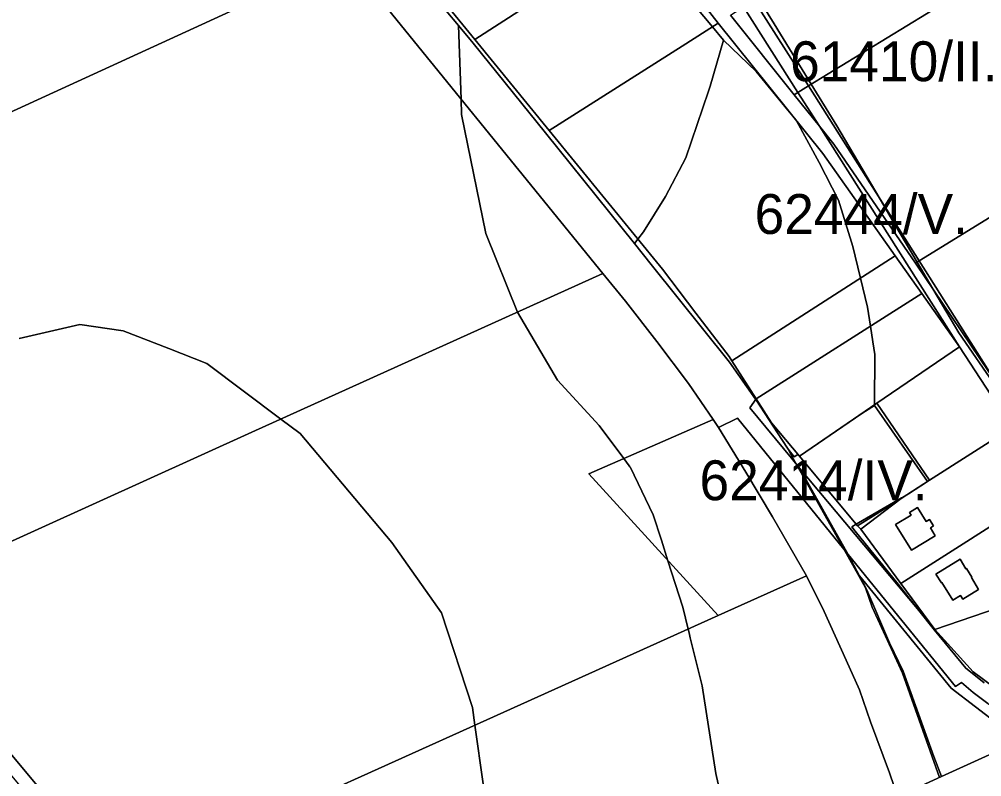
# Model space of a CAD drawing. Extents: x -522079 to -518792, y -1142400 to -1139961.
# Drawn here: x -520985.3 to -520623.1, y -1140806 to -1140520.9 of the extents above; entities that cross this region are included whole.
import ezdxf

# ---------------------------------------------------------------- set-up
doc = ezdxf.new("R2010")
doc.units = 0
for name, color, linetype in [('Hranice parcel', 7, 'Continuous'), ('Parcelní čísla', 7, 'Continuous'), ('Poz předměty', 7, 'Continuous'), ('Značky bodu BP', 7, 'Continuous'), ('Značky kultur', 7, 'Continuous')]:
    doc.layers.add(name, color=color, linetype=linetype)

msp = doc.modelspace()

# ---------------------------------------------------------------- linework, layer by layer
at = {"layer": 'Hranice parcel'}
for points in [[(-520837.71, -1140499.35), (-520813.81, -1140528.62), (-520785.9, -1140562.81), (-520743.28, -1140615.01), (-520730.64, -1140631.58), (-520718.15, -1140647.9), (-520717.09, -1140649.55), (-520707.94, -1140663.79), (-520710.41, -1140667.24), (-520694.71, -1140686.16), (-520691.52, -1140689.98), (-520673.31, -1140722.41), (-520715.02, -1140671.04), (-520722.11, -1140674.56), (-520724.12, -1140671.61), (-520733.42, -1140657.97), (-520745.42, -1140642.26), (-520757.18, -1140627.06), (-520765.71, -1140616.57), (-520862.22, -1140497.87)], [(-520620.79, -1140778.52), (-520626.26, -1140774.29), (-520630.76, -1140770.61), (-520632.98, -1140772.07), (-520673.31, -1140722.41), (-520691.52, -1140689.98), (-520667.53, -1140718.71), (-520640.71, -1140750.61), (-520626.37, -1140766.52), (-520614.11, -1140775.58)], [(-520987.34, -1140960.66), (-520896.33, -1140923.45), (-520882.47, -1140917.37), (-520708.35, -1140837.86), (-520654.73, -1140813.47), (-520638.22, -1140805.93), (-520618.93, -1140797.21)]]:
    msp.add_lwpolyline(points, dxfattribs=at)
for points in [[(-520708.82, -1140513.67), (-520688.32, -1140546.05), (-520692.27, -1140548.47), (-520712.75, -1140516.21)], [(-520688.32, -1140546.05), (-520646.64, -1140611.87), (-520648.02, -1140612.72), (-520678.73, -1140568), (-520684.19, -1140561.2), (-520692.27, -1140548.47)], [(-520581.36, -1140753.24), (-520579.16, -1140744.51), (-520580.56, -1140740.45), (-520583.71, -1140731.03), (-520599.29, -1140698.77), (-520608.35, -1140679.79), (-520611.7, -1140674.57), (-520631.48, -1140644.23), (-520684.19, -1140561.2), (-520678.73, -1140568), (-520648.02, -1140612.72), (-520617.05, -1140658.61), (-520605.12, -1140676.44), (-520598.21, -1140690.89), (-520586.97, -1140713.22), (-520580.64, -1140725.97), (-520577.29, -1140732.42), (-520576.44, -1140734.91), (-520575.25, -1140739.5), (-520574.04, -1140754.01), (-520579.46, -1140756.88), (-520580.35, -1140753)], [(-520646.64, -1140611.87), (-520617.05, -1140658.61), (-520648.02, -1140612.72)], [(-520691.52, -1140689.98), (-520694.71, -1140686.16), (-520710.41, -1140667.24), (-520707.94, -1140663.79), (-520702.26, -1140672.84), (-520691.74, -1140685.4), (-520669.79, -1140711.59), (-520668.57, -1140712.91), (-520653.49, -1140733.31), (-520640.71, -1140750.61), (-520667.53, -1140718.71)], [(-520691.74, -1140685.4), (-520662.52, -1140665.44), (-520642.72, -1140694.43), (-520653.44, -1140701.29), (-520669.79, -1140711.59)], [(-520657.77, -1140804.5), (-520664.94, -1140785.33), (-520669.15, -1140773.31), (-520674.16, -1140762.17), (-520682.43, -1140743.84), (-520689.02, -1140730.38), (-520701.8, -1140708.2), (-520711.88, -1140691.39), (-520722.11, -1140674.56), (-520715.02, -1140671.04), (-520673.31, -1140722.41), (-520669.12, -1140730.36), (-520666.3, -1140735.71), (-520657.82, -1140755.57), (-520652.69, -1140766.32), (-520641.11, -1140798.37), (-520638.22, -1140805.93), (-520654.73, -1140813.47), (-520656.02, -1140809.72)], [(-520655.5, -1140711.11), (-520649.68, -1140707.57), (-520650.3, -1140706.56), (-520647.28, -1140704.72), (-520644.04, -1140709.99), (-520642.78, -1140709.18), (-520641.28, -1140711.57), (-520642.42, -1140712.34), (-520640.64, -1140715.35), (-520649.51, -1140720.81)], [(-520594.41, -1140790.88), (-520595.39, -1140795.43), (-520616.33, -1140786.69), (-520634.59, -1140772.65), (-520669.12, -1140730.36), (-520673.31, -1140722.41), (-520632.98, -1140772.07), (-520630.76, -1140770.61), (-520626.26, -1140774.29), (-520620.79, -1140778.52), (-520609.47, -1140785.27), (-520604.74, -1140787.54), (-520595.11, -1140790.67)], [(-520624.28, -1140735.5), (-520630.26, -1140739.15), (-520631.05, -1140737.86), (-520633.92, -1140739.62), (-520638.05, -1140732.94), (-520638.3, -1140733.1), (-520640.31, -1140729.84), (-520631.24, -1140724.18), (-520629.04, -1140727.75), (-520628.87, -1140727.65), (-520626.83, -1140730.97), (-520627, -1140731.07)], [(-520616.33, -1140786.69), (-520618.93, -1140797.21), (-520638.22, -1140805.93), (-520641.11, -1140798.37), (-520652.69, -1140766.32), (-520657.82, -1140755.57), (-520666.3, -1140735.71), (-520669.12, -1140730.36), (-520634.59, -1140772.65)]]:
    msp.add_lwpolyline(points, close=True, dxfattribs=at)
at = {"layer": 'Parcelní čísla'}
for points in [[(-521174.07, -1140567.72), (-521038.29, -1140505.39), (-520903.84, -1140443.54), (-520902.4, -1140445.74), (-520890.58, -1140462.46), (-520871.65, -1140486.28), (-520862.22, -1140497.87), (-521134.28, -1140622.71), (-521175.11, -1140573.76)], [(-520837.71, -1140499.35), (-520772.84, -1140457.31), (-520749.72, -1140487.1), (-520813.81, -1140528.62)], [(-520785.9, -1140562.81), (-520813.81, -1140528.62), (-520749.72, -1140487.1), (-520722.28, -1140522.46), (-520735.82, -1140531.09)], [(-520862.22, -1140497.87), (-520765.71, -1140616.57), (-520897.82, -1140676.39), (-521036.95, -1140739.4), (-521134.28, -1140622.71)], [(-520712.75, -1140516.21), (-520692.27, -1140548.47), (-520693.7, -1140549.35), (-520717.71, -1140519.42)], [(-520722.28, -1140522.46), (-520682.96, -1140571.47), (-520655.7, -1140609.99), (-520717.09, -1140649.55), (-520718.15, -1140647.9), (-520730.64, -1140631.58), (-520743.28, -1140615.01), (-520785.9, -1140562.81), (-520735.82, -1140531.09)], [(-520693.7, -1140549.35), (-520692.27, -1140548.47), (-520684.19, -1140561.2)], [(-521187.8, -1140573.75), (-521174.07, -1140567.72), (-521175.11, -1140573.76), (-521134.28, -1140622.71), (-521036.95, -1140739.4), (-520947.33, -1140846.85), (-520890.08, -1140915.49), (-520882.47, -1140917.37), (-520896.33, -1140923.45), (-520894.6, -1140917.89), (-520952.05, -1140848.96), (-521041.47, -1140741.65), (-521139.09, -1140624.65), (-521179.71, -1140575.8)], [(-520655.7, -1140609.99), (-520645.69, -1140624.14), (-520707.94, -1140663.79), (-520717.09, -1140649.55)], [(-521036.95, -1140739.4), (-520897.82, -1140676.39), (-520765.71, -1140616.57), (-520757.18, -1140627.06), (-520745.42, -1140642.26), (-520733.42, -1140657.97), (-520724.12, -1140671.61), (-520771, -1140692.05), (-520722.34, -1140745.4), (-520809.38, -1140784.65), (-520947.33, -1140846.85)], [(-520702.26, -1140672.84), (-520707.94, -1140663.79), (-520645.69, -1140624.14), (-520631.48, -1140644.23), (-520662.52, -1140665.44), (-520691.74, -1140685.4)], [(-520722.34, -1140745.4), (-520771, -1140692.05), (-520724.12, -1140671.61), (-520722.11, -1140674.56), (-520711.88, -1140691.39), (-520701.8, -1140708.2), (-520689.02, -1140730.38)], [(-520752.69, -1140853.85), (-520890.08, -1140915.49), (-520947.33, -1140846.85), (-520809.38, -1140784.65), (-520722.34, -1140745.4), (-520689.02, -1140730.38), (-520682.43, -1140743.84), (-520674.16, -1140762.17), (-520669.15, -1140773.31), (-520664.94, -1140785.33), (-520657.77, -1140804.5), (-520656.02, -1140809.72)]]:
    msp.add_lwpolyline(points, close=True, dxfattribs=at)
msp.add_lwpolyline([(-520717.71, -1140519.42), (-520693.7, -1140549.35), (-520684.19, -1140561.2), (-520631.48, -1140644.23), (-520645.69, -1140624.14), (-520655.7, -1140609.99), (-520682.96, -1140571.47), (-520722.28, -1140522.46), (-520749.72, -1140487.1)], dxfattribs=at)
at = {"layer": 'Poz předměty'}
for points in [[(-520686.89, -1140499.45), (-520675.92, -1140498.77), (-520661.91, -1140491.42), (-520635.69, -1140488.94), (-520617.72, -1140496.63), (-520614.24, -1140500.69), (-520688.32, -1140546.05), (-520708.82, -1140513.67)], [(-520688.32, -1140546.05), (-520614.24, -1140500.69), (-520587.68, -1140531.64), (-520567.56, -1140556.74), (-520562.84, -1140560.36), (-520646.64, -1140611.87)], [(-520515.8, -1140596.49), (-520617.05, -1140658.61), (-520646.64, -1140611.87), (-520562.84, -1140560.36), (-520525.93, -1140589.59)]]:
    msp.add_lwpolyline(points, close=True, dxfattribs=at)
at = {"layer": 'Značky bodu BP'}
for points in [[(-520748.55, -1140494.92), (-520724.41, -1140523.82), (-520720.3, -1140528.75), (-520725.31, -1140546.11), (-520725.95, -1140548.02), (-520734.42, -1140573.08), (-520742.17, -1140587.7), (-520750.37, -1140600.96), (-520752.51, -1140603.7), (-520753.81, -1140605.37), (-520787.26, -1140563.73), (-520814.48, -1140529.93), (-520819.98, -1140523.33), (-520838.57, -1140501.03)], [(-520622.14, -1140770.72), (-520626.64, -1140767.02), (-520629.12, -1140765.19), (-520640.92, -1140750.89), (-520647.27, -1140742.8), (-520654.49, -1140733.61), (-520670.7, -1140713.58), (-520672, -1140711.97), (-520670.3, -1140710.98), (-520657.77, -1140703.65), (-520653.29, -1140701.03), (-520650.65, -1140699.51), (-520643.54, -1140694.95), (-520663.43, -1140666.27), (-520663.43, -1140666.06), (-520663.35, -1140647.12), (-520664.07, -1140642.39), (-520664.98, -1140636.43), (-520666.08, -1140629.29), (-520668.69, -1140618.36), (-520670.67, -1140610.09), (-520671.55, -1140606.44), (-520677.01, -1140589.08), (-520684.3, -1140574.91), (-520692.8, -1140559.2), (-520692.96, -1140558.91), (-520696.06, -1140555.15), (-520708, -1140540.63), (-520720.3, -1140528.75), (-520724.41, -1140523.82), (-520748.55, -1140494.92)], [(-520838.57, -1140501.03), (-520819.98, -1140523.33), (-520819.04, -1140550.97), (-520818.85, -1140556.8), (-520809.67, -1140601.52), (-520797.86, -1140631.12), (-520782.79, -1140656.77), (-520767.05, -1140673.87), (-520757.77, -1140686.28), (-520756.78, -1140687.61), (-520755.74, -1140689.01), (-520755.49, -1140689.33), (-520755.25, -1140689.65), (-520746.73, -1140707.41), (-520743.67, -1140716.97), (-520741.19, -1140724.73), (-520735.59, -1140742.26), (-520733.59, -1140750.47), (-520733.24, -1140751.9), (-520732.79, -1140753.72), (-520728.37, -1140771.86), (-520723.13, -1140804.75), (-520719.2, -1140822.5)], [(-520603.38, -1140680.08), (-520631.76, -1140638.92), (-520641.51, -1140622.36), (-520647.41, -1140612.34), (-520655.76, -1140598.17), (-520661.74, -1140588.03), (-520677.61, -1140561.08), (-520687.24, -1140545.38), (-520701.19, -1140522.65), (-520707.3, -1140512.68)], [(-520707.3, -1140512.68), (-520701.19, -1140522.65), (-520687.24, -1140545.38), (-520677.61, -1140561.08), (-520661.74, -1140588.03), (-520655.76, -1140598.17), (-520647.41, -1140612.34), (-520641.51, -1140622.36), (-520631.76, -1140638.92), (-520603.38, -1140680.08)], [(-520719.2, -1140822.5), (-520723.13, -1140804.75), (-520728.37, -1140771.86), (-520732.79, -1140753.72), (-520733.24, -1140751.9), (-520733.59, -1140750.47), (-520735.59, -1140742.26), (-520741.19, -1140724.73), (-520743.67, -1140716.97), (-520746.73, -1140707.41), (-520755.25, -1140689.65), (-520755.49, -1140689.33), (-520755.74, -1140689.01), (-520756.78, -1140687.61), (-520757.77, -1140686.28), (-520767.05, -1140673.87), (-520782.79, -1140656.77), (-520797.86, -1140631.12), (-520809.67, -1140601.52), (-520818.85, -1140556.8), (-520819.04, -1140550.97), (-520819.98, -1140523.33), (-520814.48, -1140529.93), (-520787.26, -1140563.73), (-520753.81, -1140605.37), (-520747.51, -1140613.22), (-520718.06, -1140649.96), (-520708.2, -1140663.95), (-520708.13, -1140664.05), (-520698.31, -1140679.15), (-520695.97, -1140682.74), (-520695.28, -1140683.98), (-520692.78, -1140688.47), (-520682.03, -1140707.78), (-520675.14, -1140720.16), (-520666.9, -1140734.95), (-520664.27, -1140742.26), (-520652.97, -1140767), (-520639.05, -1140806.31)], [(-520810.7, -1140808.74), (-520813.84, -1140786.66), (-520814.79, -1140780.02), (-520826.47, -1140744.28), (-520845.16, -1140717.91), (-520879.63, -1140676.88), (-520886.88, -1140671.43), (-520914.68, -1140650.52), (-520929.07, -1140644.91), (-520946.22, -1140638.21), (-520962.58, -1140635.86), (-520985.36, -1140641.14)], [(-520985.36, -1140641.14), (-520962.58, -1140635.86), (-520946.22, -1140638.21), (-520929.07, -1140644.91), (-520914.68, -1140650.52), (-520886.88, -1140671.43), (-520879.63, -1140676.88), (-520845.16, -1140717.91), (-520826.47, -1140744.28), (-520814.79, -1140780.02), (-520813.84, -1140786.66), (-520810.7, -1140808.74)], [(-520639.05, -1140806.31), (-520652.97, -1140767), (-520664.27, -1140742.26), (-520666.9, -1140734.95), (-520675.14, -1140720.16), (-520682.03, -1140707.78), (-520692.78, -1140688.47), (-520695.28, -1140683.98), (-520695.97, -1140682.74), (-520693.66, -1140685.62), (-520692.29, -1140684.74), (-520691.74, -1140685.4), (-520668.27, -1140669.37), (-520663.43, -1140666.27), (-520643.54, -1140694.95), (-520650.65, -1140699.51), (-520653.29, -1140701.03), (-520657.77, -1140703.65), (-520670.3, -1140710.98), (-520672, -1140711.97), (-520670.7, -1140713.58), (-520654.49, -1140733.61), (-520647.27, -1140742.8), (-520640.92, -1140750.89), (-520629.12, -1140765.19), (-520626.64, -1140767.02), (-520622.14, -1140770.72)]]:
    msp.add_lwpolyline(points, dxfattribs=at)
msp.add_lwpolyline([(-520663.43, -1140666.27), (-520668.27, -1140669.37), (-520691.74, -1140685.4), (-520692.29, -1140684.74), (-520693.66, -1140685.62), (-520695.97, -1140682.74), (-520698.31, -1140679.15), (-520708.13, -1140664.05), (-520708.2, -1140663.95), (-520718.06, -1140649.96), (-520747.51, -1140613.22), (-520753.81, -1140605.37), (-520752.51, -1140603.7), (-520750.37, -1140600.96), (-520742.17, -1140587.7), (-520734.42, -1140573.08), (-520725.95, -1140548.02), (-520725.31, -1140546.11), (-520720.3, -1140528.75), (-520708, -1140540.63), (-520696.06, -1140555.15), (-520692.96, -1140558.91), (-520692.8, -1140559.2), (-520684.3, -1140574.91), (-520677.01, -1140589.08), (-520671.55, -1140606.44), (-520670.67, -1140610.09), (-520668.69, -1140618.36), (-520666.08, -1140629.29), (-520664.98, -1140636.43), (-520664.07, -1140642.39), (-520663.35, -1140647.12), (-520663.43, -1140666.06)], close=True, dxfattribs=at)
at = {"layer": 'Značky kultur'}
for points in [[(-520662.52, -1140665.44), (-520631.48, -1140644.23), (-520611.7, -1140674.57), (-520642.72, -1140694.43)], [(-520653.49, -1140733.31), (-520668.57, -1140712.91), (-520653.44, -1140701.29), (-520642.72, -1140694.43), (-520611.7, -1140674.57), (-520608.35, -1140679.79), (-520599.29, -1140698.77)], [(-520640.71, -1140750.61), (-520653.49, -1140733.31), (-520599.29, -1140698.77), (-520583.71, -1140731.03), (-520593.04, -1140734.3)], [(-520653.44, -1140701.29), (-520668.57, -1140712.91), (-520669.79, -1140711.59)], [(-520655.5, -1140711.11), (-520649.51, -1140720.81), (-520640.64, -1140715.35), (-520642.42, -1140712.34), (-520641.28, -1140711.57), (-520642.78, -1140709.18), (-520644.04, -1140709.99), (-520647.28, -1140704.72), (-520650.3, -1140706.56), (-520649.68, -1140707.57)], [(-520624.28, -1140735.5), (-520627, -1140731.07), (-520626.83, -1140730.97), (-520628.87, -1140727.65), (-520629.04, -1140727.75), (-520631.24, -1140724.18), (-520640.31, -1140729.84), (-520638.3, -1140733.1), (-520638.05, -1140732.94), (-520633.92, -1140739.62), (-520631.05, -1140737.86), (-520630.26, -1140739.15)]]:
    msp.add_lwpolyline(points, close=True, dxfattribs=at)
msp.add_lwpolyline([(-520614.11, -1140775.58), (-520626.37, -1140766.52), (-520640.71, -1140750.61), (-520593.04, -1140734.3)], dxfattribs=at)

# ---------------------------------------------------------------- texts
at = {"layer": 'Značky bodu BP'}
for s, rotation, p in [('61410/II.', 360, (-520695.23, -1140544.26)), ('62444/V.', 0, (-520708.58, -1140601.74)), ('62414/IV.', 0, (-520729.31, -1140701.96))]:
    msp.add_text(s, height=15, rotation=rotation, dxfattribs=at).set_placement(p)

doc.saveas('drawing.dxf')
